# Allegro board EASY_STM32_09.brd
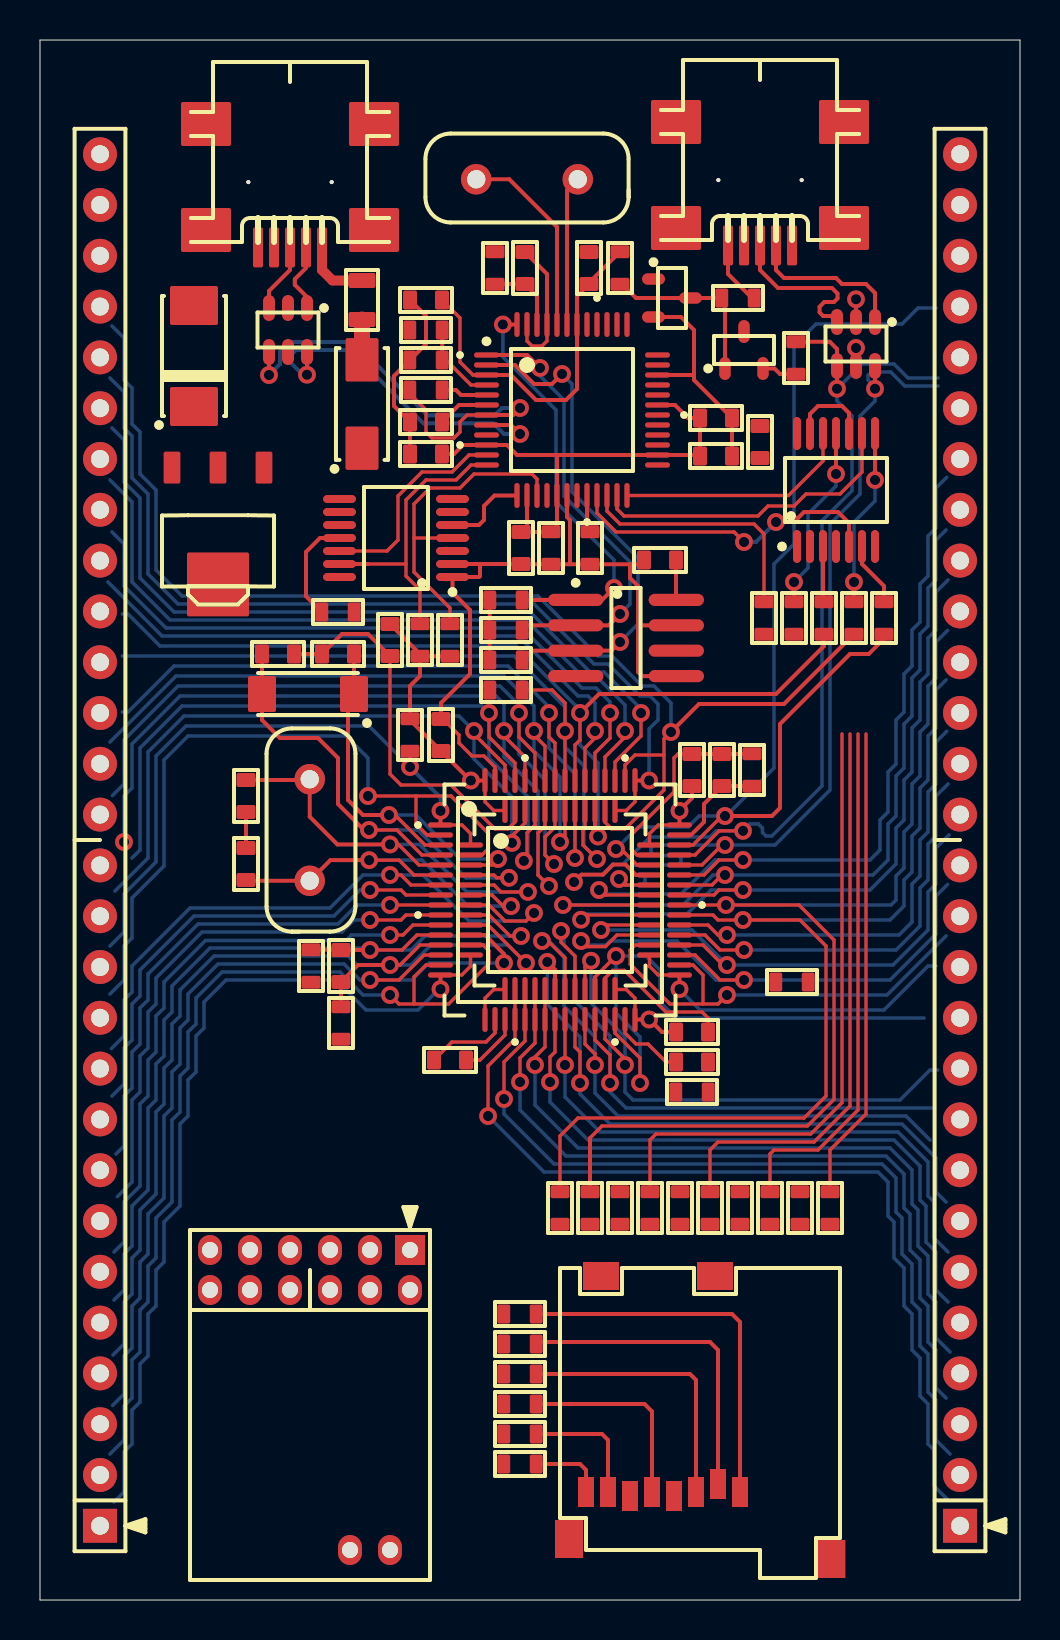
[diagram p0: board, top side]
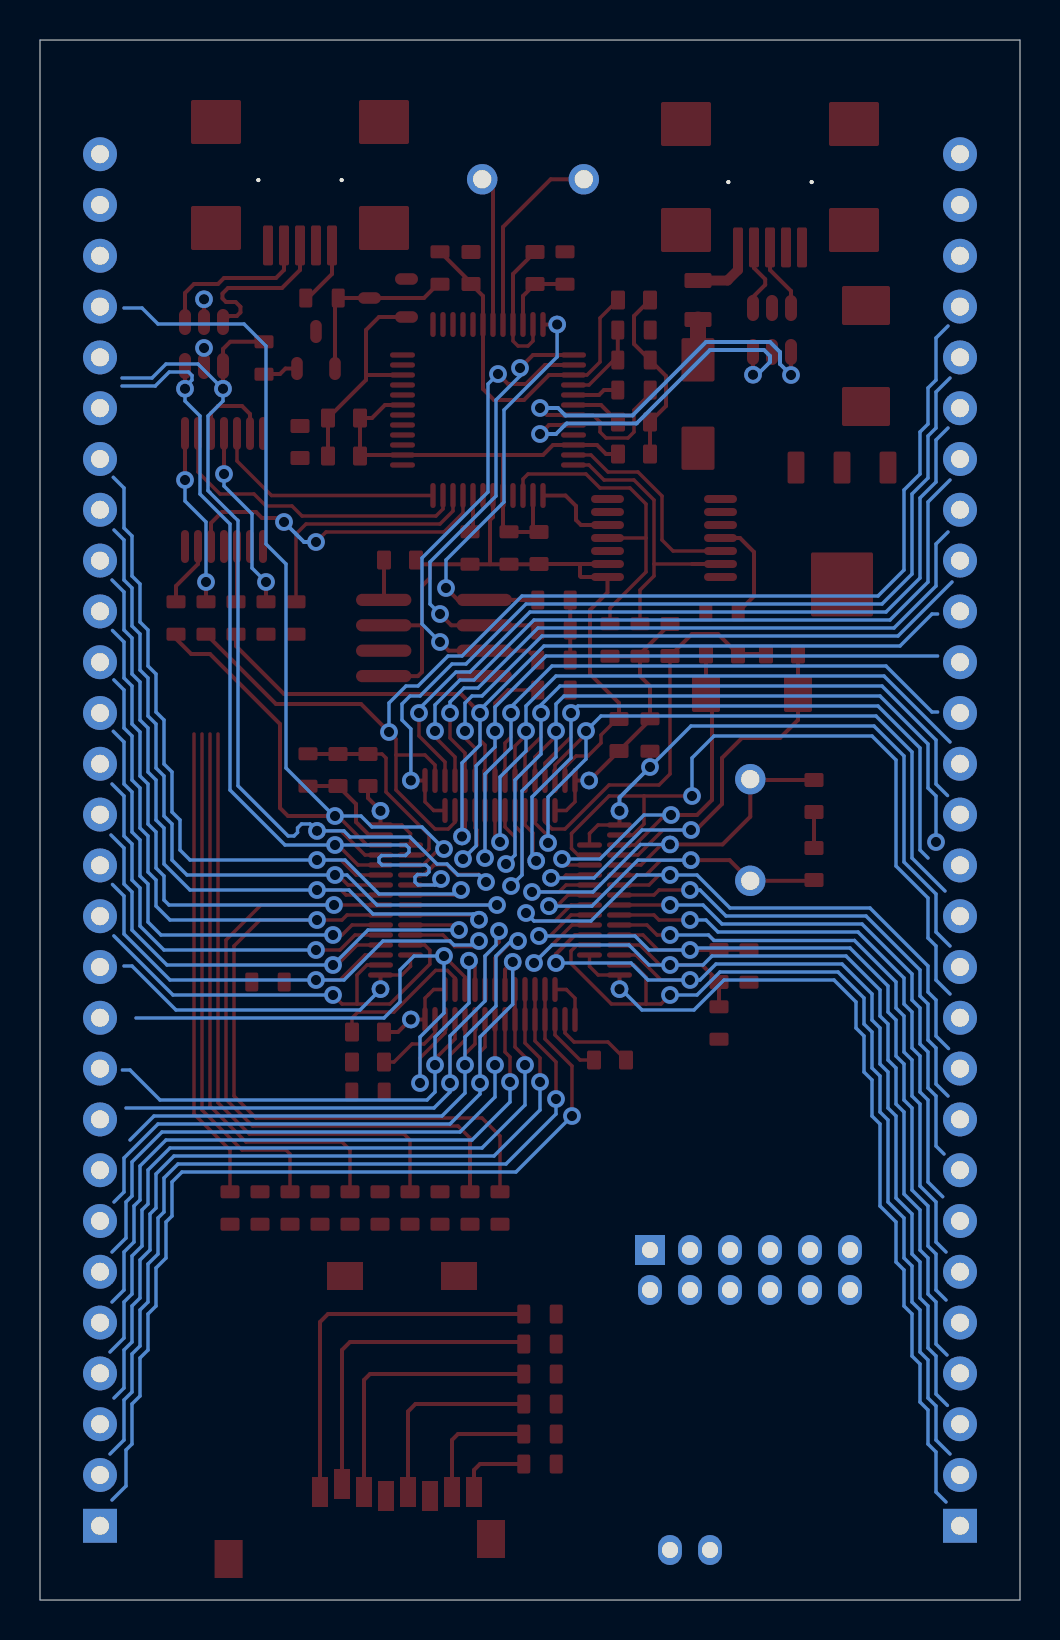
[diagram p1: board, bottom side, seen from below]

Outline 49 x 78 mm; copper layers: TOP, BOTTOM. Coordinates in mm from the lower left corner of the outline.
Outline path: 0,78 0,0 49,0 49,78 0,78

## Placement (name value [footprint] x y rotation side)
C1  22pF  [CAP0603_B]  10.3 40.2 270 top
C2  22p  [CAP0603_B]  10.3 36.8 90 top
C3  15p  [CAP0603_B]  11.9 47.3 0 top
C4  15p  [CAP0603_B]  14.9 47.3 180 top
C5  100n  [CAP0603_B]  15.05 31.7 90 top
C6  100n  [CAP0603_B]  32.6 28.4 0 top
C7  100n  [CAP0603_B]  32.6 41.5 90 top
C8  100n  [CAP0603_B]  20.05 43.25 90 top
C9  100n  [CAP0603_B]  20.5 27 180 top
C11  100n  [CAP0603_B]  19.3 65 180 top
C12  100n  [CAP0603_B]  27.45 66.6 90 top
C14  100n  [CAP0603_B]  19.3 57.3 180 top
C15  100n  [CAP0603_B]  24.05 52.6 270 top
C16  100n  [CAP0603_B]  33.8 57.2 0 top
C17  100n  [CAP0603_B]  33.8 59.1 0 top
C18  100n  [CAP0603_B]  24.25 66.6 90 top
C19  100n  [CAP0603_B]  19.3 58.9 180 top
C22  100n  [CAP0603_B]  31 52 180 top
C23  220uF  [CAP220UF]  7.7 62.2 90 top
C27  100n  [CAP0603_B]  32.6 26.9 0 top
C28  100n  [CAP0603_B]  34.1 41.5 90 top
C45  100nF  [CAP0603_B]  36 57.9 90 top
C46  100nF  [CAP0603_B]  17.5 48 270 top
D2  1N5819  [SS14]  16.1 59.8 90 top
J1  USB_MB  [HIROSE-US60-MB-5ST]  12.5 76.9 180 top
J2  USB_MB  [HIROSE-US60-MB-5ST]  36 77 180 top
J3  CON28  [CON28-1X28]  46 3.71 90 top
J4  CON28  [CON28-1X28]  3 3.71 90 top
L1  FB60R  [RES0805_B]  16.1 65 90 top
NOREF  -  [#2]  50 0 90 top
NOREF#2  -  [#2]  0 -2 0 top
Q1  C1815  [SOT-23]  35.2 62.5 0 top
Q2  C1815  [SOT-23]  31.6 65.1 270 top
R1  0R  [RES0603_B]  18.5 43.25 90 top
R2  0R  [RES0603_B]  15.05 28.85 270 top
R3  0R  [RES0603_B]  13.55 31.7 270 top
R4  470R  [RES0603_B]  22.75 66.6 270 top
R5  4K7  [RES0603_B]  19.3 63.5 0 top
R6  10K  [RES0603_B]  19.3 62 180 top
R7  10K  [RES0603_B]  27.5 52.6 270 top
R8  10K  [RES0603_B]  23.3 47 0 top
R9  10K  [RES0603_B]  23.3 48.5 0 top
R10  10K  [RES0603_B]  23.3 50 0 top
R13  1K5  [RES0603_B]  19.3 60.5 0 top
R14  100K  [RES0603_B]  25.55 52.6 270 top
R15  10K  [RES0603_B]  24 8.3 0 top
R16  10K  [RES0603_B]  24 11.3 0 top
R17  10K  [RES0603_B]  24 9.8 0 top
R18  10K  [RES0603_B]  24 12.8 0 top
R19  10K  [RES0603_B]  24 6.8 0 top
R20  10K  [RES0603_B]  24 14.3 0 top
R23  0R  [RES0603_B]  26 19.6 270 top
R24  0R  [RES0603_B]  33.5 19.6 270 top
R25  0R  [RES0603_B]  30.5 19.6 270 top
R26  0R  [RES0603_B]  36.5 19.6 270 top
R27  0R  [RES0603_B]  27.5 19.6 270 top
R28  0R  [RES0603_B]  39.5 19.6 270 top
R29  0R (DNP)  [RES0603_B]  29 19.6 90 top
R30  0R (DNP)  [RES0603_B]  35 19.6 90 top
R31  0R (DNP)  [RES0603_B]  32 19.6 90 top
R32  0R (DNP)  [RES0603_B]  38 19.6 90 top
R34  100K  [RES0603_B]  36.2 49.1 270 top
R35  100R  [RES0603_B]  39.2 49.1 270 top
R36  100R  [RES0603_B]  42.2 49.1 270 top
R37  100R  [RES0603_B]  40.7 49.1 270 top
R38  100R  [RES0603_B]  37.7 49.1 270 top
R39  100K  [RES0603_B]  19 48 90 top
R40  100K  [RES0603_B]  20.5 48 90 top
R41  100R  [RES0603_B]  23.3 45.5 0 top
R42  100R  [RES0603_B]  14.9 49.4 0 top
R43  0R  [RES0603_B]  32.6 25.4 0 top
R44  10K  [RES0603_B]  29 66.6 270 top
R45  36K  [RES0603_B]  34.9 65.1 0 top
R46  1K5  [RES0603_B]  37.8 62.1 90 top
R47  47K  [RES0603_B]  37.6 30.9 0 top
R48  0R  [RES0603_B]  35.6 41.5 90 top
REF  val  [unnamed]  18.5 17.5 180 top
U1  STM32F103RCT6  [LQFP64_MODIFIED]  26 35 0 top
U2  STM32F100  [LQFP48L_MODIFIED]  26 35 0 top
U3  FT2232D  [LQFP48L]  26.6 59.5 0 top
U4  AT93C46-10SI-2.7  [SOIC8S1JEDECM]  29.3 48.1 270 top
U5  74LVC125A  [TSOP65P640X120-14]  39.8 55.5 0 top
U6  74LVC125A  [TSOP65P640X120-14]  17.8 53.1 90 top
U7  LD1117-3V3  [SOT-223]  8.9 53.42 180 top
U10  MICRO_SD  [MICRO_SD_PUSH]  40 16.6 180 top
U11  USBLC6-2P6  [SOT23-6L]  40.8 62.8 180 top
U12  USBLC6-2P6  [SOT23-6L]  12.4 63.5 180 top
Y1  8M  [XTAL_DIP]  13.49 35.96 90 top
Y2  32.768KHz  [ABS10]  13.4 45.3 180 top
Y3  6M  [XTAL_DIP]  26.89 71.04 180 top

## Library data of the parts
C1-C9 C27 C28 = C1005_0: User Part Number: pn; Tolerance: RichardLC
C11 C12 C14-C19 C22 = CAP NP_0: User Part Number: pn; Tolerance: RichardLC
C23 = CAPACITOR POL: User Part Number: pn; Tolerance: RichardLC
C45 C46 = C1005_5: User Part Number: pn; Tolerance: RichardLC
D2 = DIODE SCHOTTKY_1: User Part Number: pn; Tolerance: RichardLC
J1 J2 = CON9_2: User Part Number: pn; Tolerance: RichardLC
J3 J4 = CON26_0: User Part Number: pn; Tolerance: RichardLC
L1 = INDUCTOR/SM_0: User Part Number: pn; Tolerance: RichardLC
Q1 Q2 = 2N3904_0: User Part Number: pn; Tolerance: RichardLC
R1-R10 R13-R20 R23-R32 R34-R48 = R_0: User Part Number: pn; Tolerance: RichardLC
REF = -: User Part Number: pn; Tolerance: RichardLC
U1 = STM32F103RCT6_2: User Part Number: pn; Tolerance: RichardLC
U2 = STM32F100_1: User Part Number: pn; Tolerance: RichardLC
U3 = FT2232D_0: User Part Number: pn; Tolerance: RichardLC
U4 = 93C46_2: User Part Number: pn; Tolerance: RichardLC
U5 U6 = 74HC125/LCC_0: User Part Number: pn; Tolerance: RichardLC
U7 = LD1117: User Part Number: pn; Tolerance: RichardLC
U10 = MOLEX_uSD_0: User Part Number: pn; Tolerance: RichardLC
U11 U12 = USBLC6-2P6: User Part Number: pn; Tolerance: RichardLC
Y1 Y3 = ZTB: Tolerance: ***; User Part Number: ***
Y2 = ZTA: User Part Number: pn; Tolerance: RichardLC

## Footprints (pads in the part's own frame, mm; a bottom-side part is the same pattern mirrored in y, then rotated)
ABS10
  custom 0.35x0.35 smd: 1(-2.3,0) 2(2.3,0)
CAP220UF
  custom 0.487x0.487 smd: 1(-2.525,0) 2(2.525,0)
CAP0603_B
  custom 0.175x0.175 smd: 1(-0.8,0) 2(0.8,0)
CON28-1X28
  rect 1.7x1.7 hole 0.9: 1(0,0)
  round 1.7 hole 0.9: 2(2.54,0) 3(5.08,0) 4(7.62,0) 5(10.16,0) 6(12.7,0) 7(15.24,0) 8(17.78,0) 9(20.32,0) 10(22.86,0) 11(25.4,0) 12(27.94,0) 13(30.48,0) 14(33.02,0) 15(35.56,0) 16(38.1,0) 17(40.64,0) 18(43.18,0) 19(45.72,0) 20(48.26,0) 21(50.8,0) 22(53.34,0) 23(55.88,0) 24(58.42,0) 25(60.96,0) 26(63.5,0) 27(66.04,0) 28(68.58,0)
HIROSE-US60-MB-5ST
  round 0.2 hole 0.9 unplated: (-2.083,6.005) (2.083,6.005)
  custom 0.125x0.125 smd: 1(-1.6,9.271) 2(-0.8,9.271) 3(0,9.271) 4(0.8,9.271) 5(1.6,9.271)
  custom 0.55x0.55 smd: 6(-4.2,3.1) 7(4.2,3.1) 8(-4.2,8.4) 9(4.2,8.4)
LQFP48L
  oval 1.25x0.27 smd: 1(-4.275,2.75) 2(-4.275,2.25) 3(-4.275,1.75) 4(-4.275,1.25) 5(-4.275,0.75) 6(-4.275,0.25) 7(-4.275,-0.25) 8(-4.275,-0.75) 9(-4.275,-1.25) 10(-4.275,-1.75) 11(-4.275,-2.25) 12(-4.275,-2.75) 25(4.275,-2.75) 26(4.275,-2.25) 27(4.275,-1.75) 28(4.275,-1.25) 29(4.275,-0.75) 30(4.275,-0.25) 31(4.275,0.25) 32(4.275,0.75) 33(4.275,1.25) 34(4.275,1.75) 35(4.275,2.25) 36(4.275,2.75)
  oval 0.27x1.25 smd: 13(-2.75,-4.275) 14(-2.25,-4.275) 15(-1.75,-4.275) 16(-1.25,-4.275) 17(-0.75,-4.275) 18(-0.25,-4.275) 19(0.25,-4.275) 20(0.75,-4.275) 21(1.25,-4.275) 22(1.75,-4.275) 23(2.25,-4.275) 24(2.75,-4.275) 37(2.75,4.275) 38(2.25,4.275) 39(1.75,4.275) 40(1.25,4.275) 41(0.75,4.275) 42(0.25,4.275) 43(-0.25,4.275) 44(-0.75,4.275) 45(-1.25,4.275) 46(-1.75,4.275) 47(-2.25,4.275) 48(-2.75,4.275)
LQFP48L_MODIFIED
  oval 1.25x0.27 smd: 1(-4.475,2.75) 2(-4.475,2.25) 3(-4.475,1.75) 4(-4.475,1.25) 5(-4.475,0.75) 6(-4.475,0.25) 7(-4.475,-0.25) 8(-4.475,-0.75) 9(-4.475,-1.25) 10(-4.475,-1.75) 11(-4.475,-2.25) 12(-4.475,-2.75) 25(4.475,-2.75) 26(4.475,-2.25) 27(4.475,-1.75) 28(4.475,-1.25) 29(4.475,-0.75) 30(4.475,-0.25) 31(4.475,0.25) 32(4.475,0.75) 33(4.475,1.25) 34(4.475,1.75) 35(4.475,2.25) 36(4.475,2.75)
  oval 0.27x1.25 smd: 13(-2.75,-4.475) 14(-2.25,-4.475) 15(-1.75,-4.475) 16(-1.25,-4.475) 17(-0.75,-4.475) 18(-0.25,-4.475) 19(0.25,-4.475) 20(0.75,-4.475) 21(1.25,-4.475) 22(1.75,-4.475) 23(2.25,-4.475) 24(2.75,-4.475) 37(2.75,4.475) 38(2.25,4.475) 39(1.75,4.475) 40(1.25,4.475) 41(0.75,4.475) 42(0.25,4.475) 43(-0.25,4.475) 44(-0.75,4.475) 45(-1.25,4.475) 46(-1.75,4.475) 47(-2.25,4.475) 48(-2.75,4.475)
LQFP64_MODIFIED
  oval 1.25x0.27 smd: 1(-5.975,3.75) 2(-5.975,3.25) 3(-5.975,2.75) 4(-5.975,2.25) 5(-5.975,1.75) 6(-5.975,1.25) 7(-5.975,0.75) 8(-5.975,0.25) 9(-5.975,-0.25) 10(-5.975,-0.75) 11(-5.975,-1.25) 12(-5.975,-1.75) 13(-5.975,-2.25) 14(-5.975,-2.75) 15(-5.975,-3.25) 16(-5.975,-3.75) 33(5.975,-3.75) 34(5.975,-3.25) 35(5.975,-2.75) 36(5.975,-2.25) 37(5.975,-1.75) 38(5.975,-1.25) 39(5.975,-0.75) 40(5.975,-0.25) 41(5.975,0.25) 42(5.975,0.75) 43(5.975,1.25) 44(5.975,1.75) 45(5.975,2.25) 46(5.975,2.75) 47(5.975,3.25) 48(5.975,3.75)
  oval 0.27x1.25 smd: 17(-3.75,-5.975) 18(-3.25,-5.975) 19(-2.75,-5.975) 20(-2.25,-5.975) 21(-1.75,-5.975) 22(-1.25,-5.975) 23(-0.75,-5.975) 24(-0.25,-5.975) 25(0.25,-5.975) 26(0.75,-5.975) 27(1.25,-5.975) 28(1.75,-5.975) 29(2.25,-5.975) 30(2.75,-5.975) 31(3.25,-5.975) 32(3.75,-5.975) 49(3.75,5.975) 50(3.25,5.975) 51(2.75,5.975) 52(2.25,5.975) 53(1.75,5.975) 54(1.25,5.975) 55(0.75,5.975) 56(0.25,5.975) 57(-0.25,5.975) 58(-0.75,5.975) 59(-1.25,5.975) 60(-1.75,5.975) 61(-2.25,5.975) 62(-2.75,5.975) 63(-3.25,5.975) 64(-3.75,5.975)
MICRO_SD_PUSH
  rect 0.8x1.5 smd: 1(5,11.2) 2(6.1,10.8) 3(7.2,11.2) 4(8.3,11.4) 5(9.4,11.2) 6(10.5,11.4) 7(11.6,11.2) 8(12.7,11.2)
  rect 1.4x1.9 smd: G1(0.43,14.55) G2(13.55,13.55)
  rect 1.8x1.4 smd: S1(6.25,0.4) S2(11.95,0.4)
RES0603_B
  custom 0.163x0.163 smd: 1(-0.812,0) 2(0.812,0)
RES0805_B
  custom 0.188x0.188 smd: 1(-0.975,0) 2(0.975,0)
SOIC8S1JEDECM
  oval 0.61x2.77 smd: 1(-1.905,-2.515) 2(-0.635,-2.515) 3(0.635,-2.515) 4(1.905,-2.515) 5(1.905,2.515) 6(0.635,2.515) 7(-0.635,2.515) 8(-1.905,2.515)
SOT23-6L
  oval 0.6x1.3 smd: 1(-0.95,-1.1) 2(0,-1.1) 3(0.95,-1.1) 4(0.95,1.1) 5(0,1.1) 6(-0.95,1.1)
SOT-23
  oval 0.58x1.15 smd: 1(-0.95,-0.925) 2(0.95,-0.925) 3(0,0.925)
SOT-223
  custom 0.21x0.21 smd: 1(-2.3,-3.195) 2(0,-3.195) 3(2.3,-3.195)
  custom 0.775x0.775 smd: 4(0,2.645)
SS14
  custom 0.412x0.412 smd: A(2.21,0) C(-2.21,0)
TSOP65P640X120-14
  oval 0.4x1.65 smd: 1(-1.95,-2.825) 2(-1.3,-2.825) 3(-0.65,-2.825) 4(0,-2.825) 5(0.65,-2.825) 6(1.3,-2.825) 7(1.95,-2.825) 8(1.95,2.825) 9(1.3,2.825) 10(0.65,2.825) 11(0,2.825) 12(-0.65,2.825) 13(-1.3,2.825) 14(-1.95,2.825)
unnamed
  rect 1.5x1.5 hole 0.8: 1(0,0)
  oval 1.194x1.499 hole 0.8: 2(0,2) 3(2,0) 4(2,2) 5(4,0) 6(4,2) 7(6,0) 8(6,2) 9(8,0) 10(8,2) 11(10,0) 12(10,2) 13(1,15) 14(3,15)
XTAL_DIP
  round 1.524 hole 0.914: 1(0,0) 2(5.08,0)

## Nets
+3V3: C6.1 C7.1 C8.1 C9.1 C14.1 C15.1 C16.1 C17.1 C45.1 C46.1 Q1.3(C) R1.2 R2.2 R14.1 R15.1 R16.1 R17.1 R18.1 R19.1 R20.1 R39.1 R40.1 R47.1 U1.19(VDD_4) U1.32(VDD_1) U1.48(VDD_2) U1.64(VDD_3) U2.24(VDD_1) U2.36(VDD_2) U2.48(VDD_3) U3.10(SI/WUA) U3.14(VCCIOA) U3.17(ADBUS6) U3.26(SI/WUB) U3.31(VCCIOB) U5.14(VCC) U6.14(VCC) U7.2(VOUT) U7.4(SH) U10.4(VDD)
+5V: C11.1 C12.1 C22.1 C23.1 D2.C R4.1 R8.1 R9.1 R10.1 R44.1 U3.3(VCC1) U3.42(VCC2) U4.8(VCC) U7.3(VIN) U11.5(VBUS) U12.5(VBUS)
GND: C1.2 C2.2 C3.2 C4.2 C6.2 C7.2 C8.2 C9.2 C11.2 C12.2 C14.2 C15.2 C16.2 C17.2 C18.2 C19.2 C22.2 C23.2 C27.2 C28.2 C45.2 C46.2 J1.5(GND) J1.6(SH1) J1.7(SH2) J1.8(SH3) J1.9(SH4) J2.5(GND) J2.6(SH1) J2.7(SH2) J2.8(SH3) J2.9(SH4) Q2.2(E) R3.2 R6.2 R7.2 R14.2 R34.2 R43.2 R45.2 R48.2 U1.18(VSS_4) U1.63(VSS_3) U2.23(VSS_1) U2.35(VSS_2) U2.47(VSS_3) U3.9(GND1) U3.18(GND2) U3.25(GND3) U3.34(GND4) U3.45(AGND) U3.47(TEST) U4.5(GND) U4.7(NC) U5.7(GND) U6.1(O\E\1\) U6.2(A1) U6.7(GND) U6.9(A3) U6.10(O\E\3\) U7.1(GND) U10.6(VSS) U11.2(GND) U12.2(GND)
VBAT: R1.1 U1.1(VBAT) U2.1(VBAT)
VDDA: C5.1 R2.1 U1.13(VDDA) U2.9(VDDA)
VSSA: C5.2 R3.1 U1.12(VSSA) U2.8(VSSA)
BOOT0: U1.60(BOOT0) U2.44(BOOT0)
EECK: R9.2 U3.1(EESK) U4.2(CLK)
EECS: R10.2 U3.48(EECS) U4.1(CS)
EEDA: R8.2 U3.2(EEDATA) U4.3(DI)
JT_SRSTN: U3.16(ADBUS7)
JTG_SELN: U5.1(O\E\1\) U5.4(O\E\2\) U5.10(O\E\3\) U5.13(O\E\4\)
NRST: R42.2 U1.7(NRST) U2.7(NRST)
OSC32_IN: C4.1 U1.3(PC14/OSC32_IN) U2.3(PC14/OSC32_IN) Y2.1
OSC32_OUT: C3.1 U1.4(PC15/OSC32/OUT) U2.4(PC15/OSC32_OUT) Y2.2
OSC_IN: C1.1 U1.5(PD0/OSC_IN) U2.5(PD0/OSC_IN) Y1.2
OSC_OUT: C2.1 U1.6(PD1/OSC_OUT) U2.6(PD1/OSC_OUT) Y1.1
PA0: U1.14(PA0-WKUP) U2.10(PA0/WKUP)
PA1: U1.15(PA1) U2.11(PA1)
PA2: U1.16(PA2) U2.12(PA2)
PA3: U1.17(PA3) U2.13(PA3)
PA4: R32.2 U1.20(PA4) U2.14(PA4)
PA5: R31.2 U1.21(PA5) U2.15(PA5)
PA6: R29.2 U1.22(PA6) U2.16(PA6)
PA7: R30.2 U1.23(PA7) U2.17(PA7)
PA8: U1.41(PA8) U2.29(PA8)
PA9: U1.42(PA9) U2.30(PA9)
PA10: U1.43(PA10) U2.31(PA10)
PA11: U1.44(PA11) U2.32(PA11) U11.6(IO1_2)
PA12: R46.2 U1.45(PA12) U2.33(PA12) U11.4(IO2_2)
PA13: R36.2 U1.46(PA13) U2.34(PA13)
PA14: R38.2 U1.49(PA14) U2.37(PA14)
PA15: R37.2 U1.50(PA15) U2.38(PA15)
PB0: U1.26(PB0) U2.18(PB0)
PB1: U1.27(PB1) U2.19(PB1)
PB2: U1.28(PB2/BOOT1) U2.20(PB2)
PB3: R35.2 U1.55(PB3) U2.39(PB3)
PB4: R41.2 U1.56(PB4) U2.40(PB4)
PB5: U1.57(PB5) U2.41(PB5)
PB6: U1.58(PB6) U2.42(PB6)
PB7: U1.59(PB7) U2.43(PB7)
PB8: U1.61(PB8) U2.45(PB8)
PB9: U1.62(PB9) U2.46(PB9)
PB10: U1.29(PB10) U2.21(PB10)
PB11: U1.30(PB11) U2.22(PB11)
PB12: U1.33(PB12) U2.25(PB12)
PB13: U1.34(PB13) U2.26(PB13)
PB14: Q2.1(B) R47.2 U1.35(PB14) U2.27(PB14)
PB15: U1.36(PB15) U2.28(PB15)
PC0: U1.8(PC0)
PC1: U1.9(PC1)
PC2: U1.10(PC2)
PC3: U1.11(PC3)
PC4: U1.24(PC4)
PC5: U1.25(PC5)
PC6: U1.37(PC6)
PC7: U1.38(PC7)
PC8: R23.1 U1.39(PC8)
PC9: R27.1 U1.40(PC9)
PC10: R28.1 U1.51(PC10)
PC11: R26.1 U1.52(PC11)
PC12: R25.1 U1.53(PC12)
PC13: U1.2(PC13/TAMPER/RTC) U2.2(PC13/TAMPER/RTC)
PD2: R24.1 U1.54(PD2)
RXD: U3.39(BDBUS1)
SRST: U3.11(ACBUS3) U6.12(A4)
SRST_OE: R39.2 U3.12(ACBUS2) U6.13(O\E\4\)
TRST: U3.13(ACBUS1) U6.5(A2)
TRST_OE: R40.2 U3.15(ACBUS0) U6.4(O\E\2\)
TXD: U3.40(BDBUS0)
USB_CLK: U3.24(ADBUS0) U5.12(A4)
USB_TDI: U3.23(ADBUS1) U5.9(A3)
USB_TDO: R34.1 U3.22(ADBUS2) U5.2(A1)
USB_TMS: U3.21(ADBUS3) U5.5(A2)
N50123: R13.1 U3.7(USBDP) U12.4(IO2_2)
N50127: C18.1 R4.2 U3.46(AVCC)
N50535: R7.1 U3.20(ADBUS4)
N50793: U3.43(XTIN) Y3.1
N50801: U3.44(XTOUT) Y3.2
N51029: D2.A L1.1 R5.1
N51243: J1.1(VBUS) L1.2
N51319: R13.2 U3.5(R\S\T\O\U\T\)
N51343: U3.8(USBDM) U12.6(IO1_2)
N51347: R5.2 R6.1 U3.4(R\E\S\E\T\)
N51363: C19.1 U3.6(3V3OUT)
N51511: U4.4(DO)
N70187: R15.2 R23.2 R29.1 U10.7(DAT0/DO)
N70219: R17.2 R25.2 R31.1 U10.5(CLK)
N70227: R18.2 R26.2 R32.1 U10.2(CD/C\S\/DAT3)
N70305: U10.S2
N70345: U10.G2
N70603: R19.2 R27.2 U10.8(DAT1/RSV)
N14914218: R16.2 R24.2 R30.1 U10.3(CMD/DI)
N14919452: R35.1 U5.3(Y1)
N14919456: R36.1 U5.6(Y2)
N14919460: R37.1 U5.8(Y3)
N14919464: R38.1 U5.11(Y4)
N14919761: R20.2 R28.2 U10.1(DAT2/NC)
N14928576: R41.1 U6.6(Y2)
N14928580: R42.1 U6.11(Y4)
N14948550: J2.1(VBUS)
N14948554: J2.2(DM) U11.1(IO1_1)
N14948558: J2.3(DP) U11.3(IO2_1)
N14952468: Q1.2(E) R46.1
N14953185: Q1.1(B) Q2.3(C) R44.2 R45.1
N14959571: J1.3(DP) U12.3(IO2_1)
N14961045: J1.2(DM) U12.1(IO1_1)
N14964930: C27.1 R43.1 U1.31(VSS_1)
N14964937: C28.1 R48.1 U1.47(VSS_2)

Pads without a net: J1 4; J2 4; J3 1 2 3 4 5 6 7 8 9 10 11 12 13 14 15 16 17 18 19 20 21 22 23 24 25 26 27 28; J4 1 2 3 4 5 6 7 8 9 10 11 12 13 14 15 16 17 18 19 20 21 22 23 24 25 26 27 28; REF 1 2 3 4 5 6 7 8 9 10 11 12 13 14; U3 19 27 28 29 30 32 33 35 36 37 38 41; U4 6; U6 3 8; U10 G1 S1

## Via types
v1: diameter 0.889, hole 0.508, TOP to BOTTOM, 109 vias

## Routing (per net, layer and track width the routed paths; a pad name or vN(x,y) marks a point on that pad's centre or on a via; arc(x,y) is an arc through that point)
+3V3: length 51.7
  TOP w0.175: U2.24 29.32,30.52 29.57,30.27 29.75,30.09 U1.32 ; U1.64 22.25,39.91 22.69,39.48 U2.48 ; U1.48 30.91,38.75 30.48,38.31 U2.36 ; C9.1 22,27 23.25,28.25 U1.19
  TOP w0.2: C46.1 19,47.3 R39.1 ; U1.32 v1(30.46,29.02) 30.48,29.02 31.1,28.4 C6.1 ; R39.1 19,46.2 18.5,45.7 R1.2 18.5,44 C8.1 21.52,40.98 v1(21.54,40.98) U1.64 ; R39.1 R40.1 ; U3.31 31.75,59.75 32.4,59.1 C17.1 C16.1 32.95,57.25 U3.26 25.8,57.25 ; 25.8,57.25 25.85,57.2 U3.17 25.85,53.71 R14.1 25.54,53.4 C15.1 24.35,53.7 U3.14 ; 25.8,57.25 23.85,57.25 23.35,57.75 U3.10 21.15,57.75 20.7,57.3 C14.1 ; U1.48 v1(31.98,39.46) 31.98,39.48 32.6,40.1 C7.1
+5V: length 24
  TOP w0.175: U3.3 21.65,61.25 21,61.9 21,64.1 C11.1
  TOP w0.2: 31.82,50.01 31.8,50.02 C22.1 ; U3.3 23.55,61.25 24.8,60 26.3,60 26.85,60.55 U3.42 26.85,65.2 C12.1 27.45,65.86 R44.1 ; R8.1 R9.1 R10.1 ; U11.5 v1(40.8,62.6)
GND: length 112.7
  TOP w0.175: U2.23 28.25,31.09 28.63,31.48 29.22,31.48 31.3,29.4 33.1,29.4 33.4,29.1 C6.2 ; C7.2 31.9,42.3 31.7,42.1 31.7,40.4 29.55,38.25 29.55,37.55 29.85,37.25 U2.35 ; U3.45 25.35,62.95 25.1,62.7 24.6,62.7 24.35,62.95 U3.47 ; C8.2 20.15,44.05 20.95,43.25 20.95,42.85 21.6,42.2 22.2,42.2 22.75,41.65 U1.63 ; U1.18 22.75,28.35 22.3,27.9 20.6,27.9 C9.2 ; C46.2 17.5,41.3 18.05,40.75 20.55,40.75 22.75,38.55 23.4,38.55 23.75,38.9 U2.47
  TOP w0.2: C8.2 20.05,44.85 21.5,46.3 21.5,49.5 20.62,50.38 20.62,51.15 21.95,51.15 22,51.2 22,51.8 ; 20.62,51.8 22,51.8 ; 22,51.8 C15.2 24.06,51.79 R14.2 26.5,51.79 ; U3.45 25.35,66.3 C18.2 ; 32.7,61.3 32.7,63.5 32.05,64.15 Q2.2 ; 32.7,61.3 32.7,61 C17.2 C16.2 ; 32.7,61.3 32.65,61.25 U3.34 ; J2.5 34.4,66.3 35.6,65.1 R45.2 ; U3.18 26.35,54.15 26.5,54 26.5,51.79 ; 29.5,51.79 29.5,51.1 29.9,50.7 29.9,48.7 ; 29.5,51.79 29.99,51.79 C22.2 ; 29.5,51.79 R7.2 26.5,51.79 ; C7.2 C28.2 35.59,42.3 R48.2 ; 29.9,48.7 29.93,48.73 31.82,48.73 ; 29.9,48.7 29.9,46.4 30.11,46.2 31.82,46.2 ; U11.2 v1(40.8,65.04) ; C2.2 C1.2 ; C14.2 C19.2 17.7,59.7 17.7,61.2 18.49,61.99 R6.2 18.5,62 19.3,62.8 19.3,64.2 C11.2 ; C46.2 16.4,48.3 15.1,48.3 C4.2 C3.2
VBAT: length 31.2
  TOP w0.175: U1.1 21.1,38.75 21.52,38.33 U2.1
  TOP w0.2: R1.1 v1(18.5,41.65) ; U1.1 v1(20.02,39.46)
  BOTTOM w0.175: v1(18.5,41.65) 16.45,43.7 7.3,43.7 5.8,42.2 5.8,36.9 4.2,35.3 4.2,33.4 3.5,32.7
  BOTTOM w0.2: v1(20.02,39.46) 20.02,40.12 v1(18.5,41.65)
VDDA: length 49.2
  TOP w0.175: v1(24.3,31.85) 22.4,33.75 U2.9 ; v1(17.5,31.75) 18,31.75 19,32.75 U1.13
  TOP w0.2: R2.1 C5.1 15.9,31.75 v1(17.5,31.75)
  BOTTOM w0.175: v1(24.3,31.85) 23.4,32.75 19.55,32.75 18.55,31.75 v1(17.5,31.75) 15.85,31.75 15.4,32.2 8.7,32.2 7,30.5 7,29.2 6.6,28.8 6.6,27 6.2,26.6 6.2,24.8 5.8,24.4 5.8,20.3 5,19.5 5,17.5 4.6,17.1 4.6,15.3 4.2,14.9 4.2,12.8 3.65,12.25
VSSA: length 45.2
  TOP w0.175: v1(16.5,32.5) 18.1,32.5 18.85,33.25 U1.12 ; U2.8 22.45,34.25 23.5,33.2 v1(24.05,33.2)
  TOP w0.2: R3.1 15.04,32.51 C5.2 v1(16.5,32.5)
  BOTTOM w0.175: 3.7,15 4.2,15.5 4.2,17.3 4.6,17.7 4.6,19.7 5.4,20.5 5.4,24.6 5.8,25 5.8,26.8 6.2,27.2 6.2,29 6.6,29.4 6.6,30.7 8.5,32.6 16.4,32.6 v1(16.5,32.5) 18.55,32.5 19.25,33.2 v1(24.05,33.2)
BOOT0: length 41.9
  TOP w0.175: v1(23.2,43.45) 23.2,43.2 24.25,42.15 U1.60 ; v1(25.45,35.7) 24.9,36.25 24.9,38.35 25.25,38.7 U2.44
  BOTTOM w0.175: v1(25.45,35.7) 24.9,36.25 24.9,40.45 23.2,42.15 v1(23.2,43.45) 23.2,44.8 22.8,45.2 7,45.2 4.6,42.8 4.6,40.6 4.2,40.2 v1(4.2,37.9)
EECK: length 22.5
  TOP w0.2: R9.2 24.35,48.73 U4.2 28.43,48.73 v1(29,49.3) ; v1(25,61.6) 24.35,62.25 U3.1
  BOTTOM w0.175: v1(25,61.6) 25,61.2 26.2,60 26.2,55.2 29.5,51.9 29.5,49.8 v1(29,49.3)
EECS: length 23.7
  TOP w0.2: U3.48 v1(23.14,63.77) ; v1(28.7,50.6) 28.1,50 R10.2 24.12,50.01 U4.1
  BOTTOM w0.175: v1(23.14,63.77) 23.14,62.16 25.8,59.5 25.8,54.9 28.7,52 v1(28.7,50.6)
EEDA: length 25
  TOP w0.2: R8.2 24.58,47.47 U4.3 28.57,47.47 v1(29,47.9) ; U3.2 23.75,61.75 24.7,60.8 25.6,60.8 v1(26.1,61.3)
  BOTTOM w0.175: v1(29,47.9) 29.9,48.8 29.9,52.1 26.6,55.4 26.6,60.8 v1(26.1,61.3)
JTG_SELN: length 4.3
  TOP w0.2: U5.10 40.45,59.35 40.1,59.7 38.9,59.7 38.5,59.3 U5.13
NRST: length 34.1
  TOP w0.175: U1.7 18.55,35.75 18.05,36.25 v1(17.5,36.25) ; v1(24.7,34.35) 24.3,33.95 23.25,33.95 22.45,34.75 U2.7
  BOTTOM w0.175: 3.57,27.57 4.2,28.2 4.2,30 4.6,30.4 4.6,31.7 7.5,34.6 14.5,34.6 16.15,36.25 v1(17.5,36.25) 19.15,36.25 21.45,33.95 24.3,33.95 v1(24.7,34.35)
OSC32_IN: length 20.8
  TOP w0.175: v1(22.9,37.05) 22.6,36.75 U2.3 ; v1(17.45,39.25) 17.75,39.25 19.25,37.75 U1.3
  TOP w0.2: C4.1 Y2.1 15.4,45 15.4,40 16.15,39.25 v1(17.45,39.25)
  BOTTOM w0.175: v1(17.45,39.25) 18.8,39.25 21,37.05 v1(22.9,37.05)
OSC32_OUT: length 26.3
  TOP w0.175: v1(23.45,36.11) 22.84,36.11 22.7,36.25 U2.4 ; U1.4 19.1,37.25 17.85,38.5 v1(16.45,38.5)
  TOP w0.2: v1(16.45,38.5) 16.2,38.5 14.9,39.8 14.9,42.1 13.9,43.1 12,43.1 11.1,44 Y2.2 C3.1
  BOTTOM w0.175: v1(23.45,36.11) 23.44,36.1 21.3,36.1 18.9,38.5 v1(16.45,38.5)
OSC_IN: length 23.5
  TOP w0.175: v1(24.4,35.4) 23.05,35.4 22.7,35.75 U2.5 ; U1.5 18.95,36.75 17.92,37.78 v1(17.5,37.78)
  TOP w0.2: v1(17.5,37.78) 14.87,37.78 13.49,39.16 Y1.2 13.45,41 C1.1
  BOTTOM w0.175: v1(24.4,35.4) 21.35,35.4 18.97,37.78 v1(17.5,37.78)
OSC_OUT: length 20.8
  TOP w0.175: U2.6 22.6,35.25 23.16,34.69 v1(23.55,34.69) ; U1.6 18.7,36.25 17.96,36.99 v1(16.46,36.99)
  TOP w0.2: v1(16.46,36.99) 14.52,36.99 Y1.1 10.34,35.96 C2.1
  BOTTOM w0.175: v1(16.46,36.99) 19.11,36.99 21.41,34.69 v1(23.55,34.69)
PA0: length 45.8
  TOP w0.175: U1.14 19.2,32.25 17.95,31 v1(16.5,31)
  TOP w0.2: U2.10 22.25,33.25 23.2,32.3 v1(23.2,31.85)
  BOTTOM w0.175: v1(23.2,31.85) 19.45,31.85 18.6,31 v1(16.5,31) 16,31 15.2,31.8 8.9,31.8 7.4,30.3 7.4,29 7,28.6 7,26.8 6.6,26.4 6.6,24.6 6.2,24.2 6.2,20.1 5.4,19.3 5.4,17.3 5,16.9 5,15.1 4.6,14.7 4.6,12.6 4.2,12.2 4.2,10.3 3.63,9.73
PA1: length 45.9
  TOP w0.175: 18.7,29.8 17.95,29.8 v1(17.5,30.25) ; 18.7,29.8 18.7,31.15 19.3,31.75 U1.15 ; 18.7,29.8 20.43,29.8 22.45,31.82 22.45,32.45 22.15,32.75 U2.11
  BOTTOM w0.175: v1(17.5,30.25) 16.15,30.25 15,31.4 9.1,31.4 7.8,30.1 7.8,28.8 7.4,28.4 7.4,26.6 7,26.2 7,24.4 6.6,24 6.6,19.9 5.8,19.1 5.8,17.1 5.4,16.7 5.4,14.9 5,14.5 5,12.4 4.6,12 4.6,10.1 4.2,9.7 4.2,8 3.5,7.3
PA2: length 43.1
  TOP w0.175: U1.16 21.09,31.25 21.52,31.68 U2.12
  TOP w0.2: U1.16 v1(20.02,30.54)
  BOTTOM w0.175: v1(20.02,30.54) 19.94,30.54 18.9,29.5 16.3,29.5 14.8,31 9.3,31 8.2,29.9 8.2,28.6 7.8,28.2 7.8,26.4 7.4,26 7.4,24.2 7,23.8 7,19.7 6.2,18.9 6.2,16.9 5.8,16.5 5.8,14.7 5.4,14.3 5.4,12.2 5,11.8 5,9.9 4.6,9.5 4.6,7.8 4.2,7.4 4.2,5.4 3.7,4.9
PA3: length 2.2
  TOP w0.175: U1.17 22.25,30.09 22.68,30.52 U2.13
PA4: length 45.6
  TOP w0.175: 23.75,30.73 U2.14 U1.20 23.75,28.05 22.4,26.7 v1(22.4,24.2)
  BOTTOM w0.175: 45.4,5 44.7,5.7 44.7,7.5 44.4,7.8 44.4,9.8 44,10.2 44,12.1 43.6,12.5 43.6,14.3 43.2,14.7 43.2,16.6 42.7,17.1 42.7,18.9 42.4,19.2 42.4,20.9 41.9,21.4 25.2,21.4 v1(22.4,24.2)
PA5: length 42.7
  TOP w0.175: 24.25,30.73 U2.15 U1.21 24.25,27.95 23.2,26.9 v1(23.2,25.05)
  BOTTOM w0.175: v1(23.2,25.05) 23.2,24.3 25.7,21.8 42.1,21.8 42.8,21.1 42.8,19.4 43.1,19.1 43.1,17.3 43.6,16.8 43.6,14.9 44,14.5 44,12.7 44.4,12.3 44.4,10.4 44.8,10 44.8,8 45.5,7.3
PA6: length 39.1
  TOP w0.175: 24.75,30.73 U2.16 U1.22 24.75,27.85 24,27.1 v1(24,25.9)
  BOTTOM w0.175: v1(24,25.9) 24,24.5 26.3,22.2 42.3,22.2 43.2,21.3 43.2,19.6 43.5,19.3 43.5,17.5 44,17 44,15.1 44.4,14.7 44.4,12.9 44.8,12.5 44.8,10.6 45.3,10.1
PA7: length 36.3
  TOP w0.175: v1(24.75,26.75) 24.75,27.15 25.25,27.65 U1.23 U2.17 25.25,30.73
  BOTTOM w0.175: v1(24.75,26.75) 24.75,24.75 26.9,22.6 42.5,22.6 43.6,21.5 43.6,19.8 43.9,19.5 43.9,17.7 44.4,17.2 44.4,15.3 44.8,14.9 44.8,13.1 45.5,12.4
PA8: length 39
  TOP w0.175: v1(35.15,35.5) 33.95,35.5 33.7,35.25 U1.41 ; U2.29 27.3,34.25 27.06,34.01 v1(27.05,34.01)
  BOTTOM w0.175: v1(27.05,34.01) 27.34,34.3 32.35,34.3 33.55,35.5 v1(35.15,35.5) 41.5,35.5 42.8,36.8 42.8,38.6 43.2,39 43.2,41 43.6,41.4 43.6,43.6 44,44 44,45.9 44.4,46.3 44.4,48.1 44.8,48.5 44.8,50.4 45.4,51
PA9: length 41.7
  TOP w0.175: v1(26.15,34.75) U2.30 ; v1(34.25,36.25) 34.1,36.25 33.6,35.75 U1.42
  BOTTOM w0.175: 45.3,53.5 44.8,53 44.8,51 44.4,50.6 44.4,48.7 44,48.3 44,46.5 43.6,46.1 43.6,44.2 43.2,43.8 43.2,41.6 42.8,41.2 42.8,39.2 42.4,38.8 42.4,37 41.65,36.25 v1(34.25,36.25) 33.65,36.25 32.15,34.75 v1(26.15,34.75)
PA10: length 41.2
  TOP w0.175: U2.31 28.3,35.25 28.05,35.5 v1(27.95,35.5) ; U1.43 33.2,36.25 33.95,37 v1(35.15,37)
  BOTTOM w0.175: 45.34,56.14 44.8,55.6 44.8,53.6 44.4,53.2 44.4,51.2 44,50.8 44,48.9 43.6,48.5 43.6,46.7 43.2,46.3 43.2,44.4 42.8,44 42.8,41.8 42.4,41.4 42.4,39.4 42,39 42,37.5 41.5,37 v1(35.15,37) 33.75,37 32.05,35.3 28.15,35.3 v1(27.95,35.5)
PA11: length 48.7
  TOP w0.175: U1.44 33.1,36.75 34.1,37.75 v1(34.25,37.75) ; v1(28.95,36.05) 29.25,35.75 U2.32
  TOP w0.2: U11.6 v1(41.75,60.56)
  BOTTOM w0.175: v1(28.95,36.05) 29.25,35.75 30.1,35.75 30.25,35.9 30.25,36.15 30.12,36.27 29.68,36.27 29.55,36.4 29.55,36.6 29.7,36.75 31.9,36.75 32.05,36.9 32.05,37.1 31.93,37.23 30.73,37.23 30.55,37.4 30.55,37.6 30.7,37.75 v1(34.25,37.75) 36.75,37.75 39.5,40.5 39.5,53.8 41,55.3 41,59.2 41.75,59.95 v1(41.75,60.56) 41.75,60.65 41.4,61 41.4,61.23 41.58,61.4 42.53,61.4 43.23,60.7 44.9,60.7
PA12: length 53.9
  TOP w0.175: U1.45 32.75,37.25 33.96,38.46 v1(35.15,38.46)
  TOP w0.2: v1(26.7,35.9) 27.07,36.27 28.15,36.27 28.65,36.77 29.28,36.77 29.8,36.25 U2.33 ; R46.2 39.49,62.91 39.85,62.55 U11.4 v1(39.85,60.56)
  BOTTOM w0.175: 44.9,61.1 43.4,61.1 42.7,61.8 41.1,61.8 39.86,60.56 v1(39.85,60.56) 39.85,59.95 40.6,59.2 40.6,55.47 39.1,53.97 39.1,40.71 36.59,38.2 36.3,38.2 36.12,38.38 36.12,38.6 35.92,38.8 35.49,38.8 v1(35.15,38.46) 33.81,38.46 33.5,38.15 30.5,38.15 29.15,36.8 28.65,36.8 28.1,36.25 27.05,36.25 v1(26.7,35.9)
PA13: length 58.2
  TOP w0.175: v1(34.25,39.2) 34.1,39.2 32.65,37.75 U1.46 ; v1(28.8,37.55) 29.05,37.55 29.85,36.75 U2.34
  TOP w0.2: v1(34.25,39.2) 36.6,39.2 37,39.6 37,43.8 40.5,47.3 41.44,47.3 42.2,48.06 R36.2
  BOTTOM w0.175: 44.8,64.6 43.9,64.6 43.1,63.8 38.8,63.8 37.7,62.7 37.7,52.8 36.7,51.8 36.7,41.6 34.3,39.2 v1(34.25,39.2) 32.95,39.2 32.4,38.65 29.9,38.65 v1(28.8,37.55)
PA14: length 45.7
  TOP w0.175: U2.37 29.32,39.48 29.75,39.91 U1.49
  TOP w0.2: U1.49 v1(30.46,40.98)
  BOTTOM w0.175: 3.5,61.1 4.2,60.4 4.2,58.6 4.6,58.2 4.6,56.1 5.4,55.3 5.4,51.3 6.9,49.8 24.7,49.8 27.7,46.8 28.4,46.8 30,45.2 30.5,45.2 30.9,44.8 30.9,44 30.46,43.56 v1(30.46,40.98)
PA15: length 64.7
  TOP w0.175: 31.2,42.25 31.2,43.05 v1(31.55,43.4) ; 31.2,42.25 29.75,42.25 29.25,41.75 U1.50 ; 31.2,42.25 31.2,40.5 29.25,38.55 28.59,38.55 28.25,38.89 U2.38
  TOP w0.2: R37.2 40.69,48.29 37.2,44.8 32.95,44.8 v1(31.55,43.4)
  BOTTOM w0.175: 3.6,63.7 4.2,63.1 4.2,61 4.6,60.6 4.6,58.8 5,58.4 5,56.3 5.8,55.5 5.8,51.5 7.1,50.2 24.9,50.2 27.9,47.2 28.6,47.2 30.1,45.7 30.7,45.7 31.55,44.85 v1(31.55,43.4)
PB0: length 33.6
  TOP w0.175: v1(27,25.85) 27,27.4 26.75,27.65 U1.26
  TOP w0.2: U2.18 25.75,31.52 v1(25.36,31.9)
  BOTTOM w0.175: v1(25.36,31.9) 25.36,29.79 27,28.15 v1(27,25.85) 27,25.3 28.5,23.8 43.1,23.8 44.8,22.1 44.8,20.4 45.3,19.9
PB1: length 32.2
  TOP w0.175: v1(27.75,26.75) 27.75,27.3 27.25,27.8 U1.27 ; U2.19 26.25,32.1 25.4,32.95 v1(25.1,32.95)
  BOTTOM w0.175: v1(25.1,32.95) 25.45,32.95 26.2,32.2 26.2,29.7 27.75,28.15 v1(27.75,26.75) 27.75,25.35 28.9,24.2 43.3,24.2 44.5,23
PB2: length 32.3
  TOP w0.175: v1(26.05,33.45) 26.05,32.89 26.75,32.19 U2.20 ; U1.28 27.75,28 28.5,27.25 v1(28.5,25.85)
  BOTTOM w0.175: v1(26.05,33.45) 26.2,33.3 26.2,32.75 26.75,32.2 26.75,29.95 28.5,28.2 v1(28.5,25.85) 28.5,25.4 29.3,24.6 44.7,24.6
PB3: length 50.6
  TOP w0.175: v1(27,44.35) 27,43 26.75,42.75 U1.55
  TOP w0.2: R35.2 39.2,47.7 36.8,45.3 27.95,45.3 v1(27,44.35) ; U2.39 27.75,38.33 v1(27.9,38.17)
  BOTTOM w0.175: 4.11,49.3 4.4,49.3 6,47.7 23.8,47.7 27,44.5 v1(27,44.35) 27,42.75 27.9,41.85 v1(27.9,38.17)
PB4: length 40.5
  TOP w0.175: U1.56 v1(26.25,43.45) 26.25,44.85 25.6,45.5 R41.2 ; v1(27.85,37.05) 27.15,37.75 27.15,38.5 27.25,38.6 U2.40
  BOTTOM w0.175: v1(27.85,37.05) 27.19,37.71 27.19,41.71 26.25,42.65 v1(26.25,43.45) 26.25,44.65 23.7,47.2 4.11,47.2
PB5: length 37.1
  TOP w0.175: v1(25.45,44.35) 25.45,43.15 25.75,42.85 U1.57 ; U2.41 v1(26.75,37.1)
  BOTTOM w0.175: 4.11,44.4 4.4,44.4 6.7,46.7 23.4,46.7 25.45,44.65 v1(25.45,44.35) 25.45,42.6 26.75,41.3 v1(26.75,37.1)
PB6: length 34.9
  TOP w0.175: v1(24.7,43.45) 24.7,43.25 25.25,42.7 U1.58 ; U2.42 26.25,38.15 v1(26,37.9)
  BOTTOM w0.175: v1(26,37.9) 26,41.15 24.7,42.45 v1(24.7,43.45) 24.7,44.7 23.2,46.2 6.8,46.2 3.5,42.9
PB7: length 39.7
  TOP w0.175: v1(23.95,44.35) 23.95,43.15 24.75,42.35 U1.59 ; v1(25.7,36.8) 25.25,37.25 25.25,38.15 25.75,38.65 U2.43
  BOTTOM w0.175: 3.62,40.22 4.2,40.8 4.2,43 6.9,45.7 23,45.7 23.95,44.75 v1(23.95,44.35) 23.95,42.3 25.25,41 25.25,37.25 v1(25.7,36.8)
PB8: length 39.1
  TOP w0.175: v1(22.45,44.35) 22.45,43.15 23.75,41.85 U1.61 ; v1(24.19,36.95) 24.35,37.11 24.35,38.35 24.75,38.75 U2.45
  BOTTOM w0.175: 4.6,37.1 5,37.5 5,42.6 7.1,44.7 22.1,44.7 v1(22.45,44.35) 22.45,42.1 24.4,40.15 24.4,37.16 v1(24.19,36.95)
PB9: length 36.4
  TOP w0.175: U2.46 24.25,38.85 23.6,38.2 v1(23.6,37.85) ; v1(21.7,43.45) 21.7,43.3 23.25,41.75 U1.62
  BOTTOM w0.175: 3.75,35.45 5.4,37.1 5.4,42.4 7.2,44.2 20.95,44.2 v1(21.7,43.45) 21.7,42.05 23.6,40.15 v1(23.6,37.85)
PB10: length 27.9
  TOP w0.175: U1.29 28.25,28.05 29.25,27.05 v1(29.25,26.75) ; v1(27.55,31.96) 27.25,31.66 U2.21
  BOTTOM w0.175: 44.89,26.5 44.5,26.5 43,25 29.65,25 29.25,25.4 v1(29.25,26.75) 29.25,28.15 27.55,29.85 v1(27.55,31.96)
PB11: length 30.3
  TOP w0.175: v1(28.8,32.2) 27.75,31.15 U2.22 ; U1.30 28.75,28.35 30,27.1 v1(30,25.85)
  BOTTOM w0.175: 44.2,29.1 31.8,29.1 31,29.9 31,31.5 30.3,32.2 v1(28.8,32.2) 28.8,29.35 30,28.15 v1(30,25.85)
PB12: length 17.1
  TOP w0.175: U2.25 30.48,31.68 30.91,31.25 U1.33
  TOP w0.2: U1.33 v1(31.98,30.54)
  BOTTOM w0.175: v1(31.98,30.54) 31.98,30.52 33,29.5 42.2,29.5 44.4,31.7 44.8,31.7
PB13: length 22.6
  TOP w0.175: 33.15,29.8 31.5,29.8 29.51,31.79 29.51,32.49 29.76,32.75 U2.26 ; 33.15,29.8 33.15,31.25 32.65,31.75 U1.34 ; 33.15,29.8 33.9,29.8 v1(34.35,30.25)
  BOTTOM w0.175: 45.31,33.21 42.35,30.25 v1(34.35,30.25)
PB14: length 29.9
  TOP w0.175: U2.27 28.85,33.25 28.27,32.67 27.33,32.67 v1(27.05,32.95) ; U1.35 32.75,32.25 34,31 v1(35.2,31)
  BOTTOM w0.175: v1(27.05,32.95) 27.25,32.75 28.3,32.75 28.5,32.95 31.85,32.95 33.8,31 v1(35.2,31) 42.5,31 44.8,33.3 44.8,35.2 45.38,35.78
PB15: length 28.3
  TOP w0.175: v1(28.05,33.5) 28.3,33.75 U2.28 ; U1.36 33.15,32.75 34.15,31.75 v1(34.35,31.75)
  BOTTOM w0.175: 45.45,38.25 44.8,37.6 44.8,35.8 44.4,35.4 44.4,33.5 42.65,31.75 v1(34.35,31.75) 32.6,33.5 v1(28.05,33.5)
PC0: length 23.7
  TOP w0.175: U1.8 18.3,35.25 18.05,35.5 v1(16.5,35.5)
  BOTTOM w0.175: v1(16.5,35.5) 16,35.5 14.7,34.2 7.7,34.2 5,31.5 5,30.2 4.6,29.8 4.6,28 4.2,27.6 4.2,25.8 3.6,25.2
PC1: length 25.7
  TOP w0.175: U1.9 v1(17.5,34.75)
  BOTTOM w0.175: 3.8,22.3 4.2,22.7 4.2,25.2 4.6,25.6 4.6,27.4 5,27.8 5,29.6 5.4,30 5.4,31.3 7.9,33.8 14.9,33.8 15.85,34.75 v1(17.5,34.75)
PC2: length 27.3
  TOP w0.175: v1(16.5,34) 18.05,34 18.3,34.25 U1.10
  BOTTOM w0.175: v1(16.5,34) 15.7,34 15.1,33.4 8.1,33.4 5.8,31.1 5.8,29.8 5.4,29.4 5.4,27.6 5,27.2 5,25.4 4.6,25 4.6,20.9 3.86,20.16
PC3: length 29.5
  TOP w0.175: v1(17.5,33.25) 18.15,33.25 18.65,33.75 U1.11
  BOTTOM w0.175: 3.7,17.4 4.2,17.9 4.2,19.9 5,20.7 5,24.8 5.4,25.2 5.4,27 5.8,27.4 5.8,29.2 6.2,29.6 6.2,30.9 8.27,32.98 15.3,32.98 15.57,33.25 v1(17.5,33.25)
PC4: length 31.4
  TOP w0.175: v1(25.5,25.9) 25.5,27.15 25.75,27.4 U1.24
  BOTTOM w0.175: 45.4,14.9 44.8,15.5 44.8,17.4 44.3,17.9 44.3,19.7 44,20 44,21.7 42.7,23 27.4,23 25.5,24.9 v1(25.5,25.9)
PC5: length 28.3
  TOP w0.175: U1.25 v1(26.25,26.75)
  BOTTOM w0.175: 45.4,17.4 44.7,18.1 44.7,19.9 44.4,20.2 44.4,21.9 42.9,23.4 28,23.4 26.25,25.15 v1(26.25,26.75)
PC6: length 20.5
  TOP w0.175: v1(35.2,32.5) 34,32.5 33.25,33.25 U1.37
  BOTTOM w0.175: v1(35.2,32.5) 42.8,32.5 44,33.7 44,35.6 44.4,36 44.4,37.8 44.8,38.2 44.8,40.2 45.4,40.8
PC7: length 22.4
  TOP w0.175: U1.38 33.4,33.75 33.9,33.25 v1(34.35,33.25)
  BOTTOM w0.175: 45.34,43.44 44.8,42.9 44.8,40.8 44.4,40.4 44.4,38.4 44,38 44,36.2 43.6,35.8 43.6,33.9 42.95,33.25 v1(34.35,33.25)
PC8: length 52.9
  TOP w0.175: U1.39 33.65,34.25 33.9,34 v1(35.15,34) 38,34 39.3,32.7 39.3,25.2 38.2,24.1 26.9,24.1 26,23.2 R23.1
  BOTTOM w0.175: 45.31,46.01 44.8,45.5 44.8,43.6 44.4,43.2 44.4,41 44,40.6 44,38.6 43.6,38.2 43.6,36.4 43.2,36 43.2,34.7 42.5,34 v1(35.15,34)
PC9: length 55.3
  TOP w0.175: U1.40 v1(34.3,34.75) 37.95,34.75 39.7,33 39.7,25.03 38.37,23.7 28.1,23.7 27.5,23.1
  TOP w0.2: 27.5,23.1 R27.1
  BOTTOM w0.175: 45.38,48.48 44.8,47.9 44.8,46.1 44.4,45.7 44.4,43.8 44,43.4 44,41.2 43.6,40.8 43.6,38.8 43.2,38.4 43.2,36.6 42.8,36.2 42.8,35 42.55,34.75 v1(34.3,34.75)
PC10: length 63.6
  TOP w0.175: 41.3,43.3 41.3,24.3 39.5,22.5 R28.1 ; v1(30.05,44.35) 30.05,43.2 28.75,41.9 U1.51
  BOTTOM w0.175: 3.6,58.6 4.2,58 4.2,55.9 5,55.1 5,51.1 6.7,49.4 24.5,49.4 27.5,46.4 28.2,46.4 30.05,44.55 v1(30.05,44.35)
PC11: length 62.9
  TOP w0.175: R26.1 36.5,22.3 36.7,22.5 38.9,22.5 40.9,24.5 40.9,43.3 ; v1(29.25,43.45) 29.25,43.15 28.25,42.15 U1.52
  BOTTOM w0.175: v1(29.25,43.45) 29.25,44.75 28,46 27.3,46 24.3,49 6.5,49 4.6,50.9 4.6,54.9 3.5,56
PC12: length 65.3
  TOP w0.175: U1.53 27.75,42.35 28.5,43.1 v1(28.5,44.35) ; 40.1,43.3 40.1,24.87 38.53,23.3 30.8,23.3 30.5,23 R25.1
  BOTTOM w0.175: 3.6,53.4 4.2,52.8 4.2,50.7 6.3,48.6 24.1,48.6 27.1,45.6 27.8,45.6 28.5,44.9 v1(28.5,44.35)
PC13: length 37.3
  TOP w0.175: U1.2 19.35,38.25 18.8,38.8 18.8,40.2 ; U2.2 22.1,37.25 22.43,37.58 22.43,38.33 20.55,40.2 18.8,40.2 ; 18.8,40.2 v1(16.4,40.2)
  BOTTOM w0.175: 3.5,30.3 4.2,31 4.2,32.7 4.6,33.1 4.6,35.1 6.2,36.7 6.2,42 7.4,43.2 15.3,43.2 16.4,42.1 v1(16.4,40.2)
PD2: length 59.5
  TOP w0.175: 40.5,43.3 40.5,24.7 38.7,22.9 33.9,22.9 33.5,22.5 R24.1 ; v1(27.75,43.45) 27.75,43.1 27.25,42.6 U1.54
  BOTTOM w0.175: 3.4,50.9 6.1,48.2 23.9,48.2 26.9,45.2 27.4,45.2 27.75,44.85 v1(27.75,43.45)
SRST: length 10.6
  TOP w0.175: U6.12 17.35,52.45 17.9,53 17.9,55.2 19.1,56.4 20.6,56.4 21.45,57.25 U3.11
SRST_OE: length 14.6
  TOP w0.175: 18.3,51.8 16.4,51.8 ; 18.3,51.8 18.3,55 19.3,56 20.8,56 21.55,56.75 U3.12 ; 18.3,51.8 18.3,51.2 19,50.5 R39.2
  TOP w0.2: 16.4,51.8 U6.13
TRST: length 4.2
  TOP w0.2: 20.62,53.75 21.95,53.75 22.2,54 22.2,54.7 22.73,55.23 U3.13
TRST_OE: length 16.4
  TOP w0.175: U3.15 24.85,56.05 24.6,56.3 21.7,56.3 21,55.6 19.5,55.6 18.7,54.8 18.7,53.1 ; 18.7,53.1 18.7,51.4 20.5,49.6 R40.2 ; 18.7,53.1 20.62,53.1
USB_CLK: length 11.9
  TOP w0.175: U3.24 37.42,55.23 39.15,56.95 U5.12
USB_TDI: length 15.9
  TOP w0.175: U3.23 28.85,54.55 29.2,54.2 35.9,54.2 36.4,54.7 37.7,54.7 38.3,55.3 40,55.3 41.1,56.4 U5.9
USB_TDO: length 12.5
  TOP w0.175: U3.22 28.35,54.45 29,53.8 35.7,53.8 36.2,53.3 R34.1
USB_TMS: length 16.1
  TOP w0.175: v1(35.2,52.9) 34.7,53.4 28.8,53.4 27.85,54.35 U3.21
  TOP w0.2: U5.5 40.45,53.85 39.9,54.4 38.2,54.4 37.9,54.1 37,54.1 v1(36.8,53.9)
  BOTTOM w0.2: v1(35.2,52.9) 35.8,52.9 v1(36.8,53.9)
N50123: length 24.6
  TOP w0.175: R13.1 18.49,60.31 19.3,59.5 19.3,58.4 19.6,58.1 20.7,58.1 21,58.4 21,58.9 21.35,59.25 U3.7
  TOP w0.2: U3.7 23.65,59.25 v1(24,59.6) ; U12.4 v1(11.45,61.25)
  BOTTOM w0.2: v1(11.45,61.25) 12,61.8 12,62.4 12.5,62.9 15.7,62.9 19.37,59.23 22.73,59.23 23.1,59.6 v1(24,59.6)
N50127: length 3.8
  TOP w0.2: R4.2 22.76,65.8 C18.1 24.85,65.2 U3.46
N50535: length 1.9
  TOP w0.2: U3.20 27.35,53.56 R7.1
N50793: length 7.5
  TOP w0.2: Y3.1 26.35,70.5 U3.43
N50801: length 9.9
  TOP w0.2: Y3.2 23.46,71.04 25.85,68.65 U3.44
N51029: length 2
  TOP w0.8: L1.1 D2.A
N51243: length 3.3
  TOP w0.5: L1.2 14.62,65.97 14.1,66.5 J1.1
N51319: length 2.3
  TOP w0.2: U3.5 21.05,60.25 20.8,60.5 R13.2
N51343: length 17.8
  TOP w0.2: U12.6 v1(13.35,61.26) ; U3.8 23.55,58.75 v1(24,58.3)
  BOTTOM w0.2: v1(13.35,61.26) 13.14,61.26 12.5,61.9 12.5,62.2 12.8,62.5 15.5,62.5 19.17,58.83 22.67,58.83 23.2,58.3 v1(24,58.3)
N51347: length 4.2
  TOP w0.175: R6.1 20.3,62 21.55,60.75 U3.4
  TOP w0.2: R5.2 R6.1
N51363: length 2.6
  TOP w0.2: U3.6 20.95,59.75 C19.1
N70187: length 6.3
  TOP w0.2: U10.7 28.4,8 28.1,8.3 R15.2
N70219: length 10
  TOP w0.2: U10.5 30.6,9.43 30.23,9.8 R17.2
N70227: length 16
  TOP w0.2: R18.2 24.91,12.9 33.5,12.9 33.9,12.5 U10.2
N70603: length 3.7
  TOP w0.2: U10.8 27.3,6.5 27,6.8 R19.2
N14914218: length 13.7
  TOP w0.2: R16.2 32.5,11.3 32.8,11 U10.3
N14919452: length 2.8
  TOP w0.2: R35.1 39.15,49.96 U5.3
N14919456: length 3.2
  TOP w0.2: U5.6 41.1,51.8 42.2,50.7 R36.1
N14919460: length 8.8
  TOP w0.2: v1(40.7,50.9) R37.1 ; U5.8 v1(41.75,56)
  BOTTOM w0.175: v1(41.75,56) 41.75,54.95 40.7,53.9 v1(40.7,50.9)
N14919464: length 9.3
  TOP w0.2: U5.11 v1(39.8,56.3) ; v1(37.7,50.9) R38.1
  BOTTOM w0.175: v1(37.7,50.9) 38.4,51.6 38.4,54.3 39.8,55.7 v1(39.8,56.3)
N14919761: length 18.9
  TOP w0.2: R20.2 34.6,14.3 35,13.9 U10.1
N14928580: length 5.3
  TOP w0.2: U6.11 14,53.1 13.3,52.4 13.3,50.19 R42.1
N14948554: length 8.1
  TOP w0.2: U11.1 41.75,65.35 41.3,65.8 40.1,65.8 39.8,66.1 37.2,66.1 36.8,66.5 J2.2
N14948558: length 8.3
  TOP w0.2: U11.3 39.55,64.2 39.16,64.2 38.98,64.38 38.98,64.66 39.22,64.9 39.7,64.9 39.88,65.08 39.88,65.32 39.6,65.6 36.9,65.6 36,66.5 J2.3
N14952468: length 1.8
  TOP w0.2: R46.1 37.79,61.3 37,61.3 36.73,61.58 Q1.2
N14953185: length 9
  TOP w0.2: Q1.1 34.25,64.94 R45.1 Q2.3 29.8,65.1 29.11,65.79 R44.2
N14959571: length 3.5
  TOP w0.2: U12.3 11.45,65.45 12.5,66.5 J1.3
N14961045: length 3.5
  TOP w0.2: J1.2 13.3,66.6 12.74,66.04 12.74,65.76 13.35,65.15 U12.1
N14964930: length 3.8
  TOP w0.175: U1.31 29.25,28.35 29.8,27.8 30.4,27.8 31.3,26.9 C27.1
N14964937: length 5.2
  TOP w0.2: R48.1 35.59,40.7 C28.1 33.2,39.8 33.2,38.9 32.55,38.25 U1.47

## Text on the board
DIMENSION: FIGURE | SIZE | 0.508 | 0.8 | 0.8999 | 0.9144 | 1.0 | 2.4 | DRILL CHART: TOP to BOTTOM | ALL UNITS ARE IN MILLIMETERS | PLATED | QTY | 121 | 14 | 200 | 2 | 4
